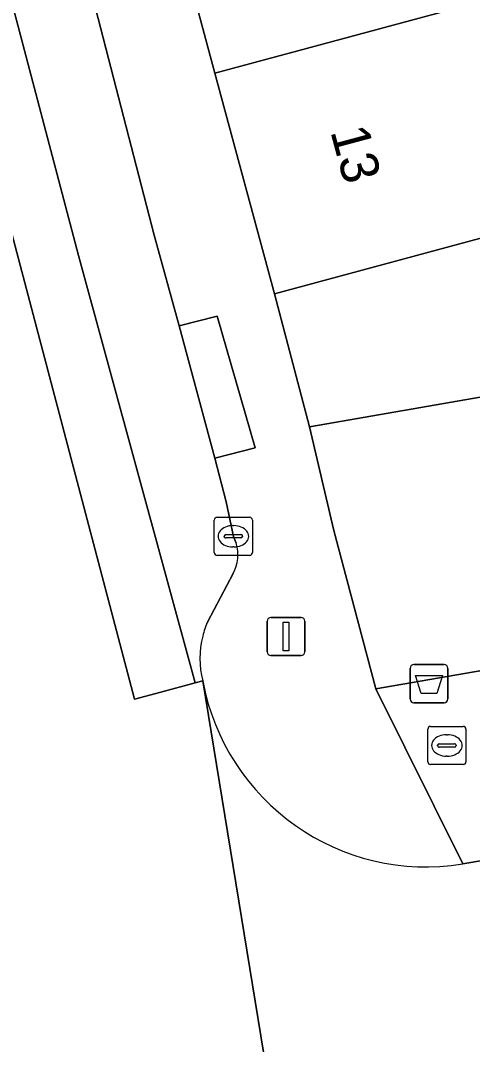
# Model space of a CAD drawing. Extents: x 159371 to 159986, y 382987 to 383597.
# Drawn here: x 159702.32 to 159714.18, y 383315.4 to 383342.22 of the extents above; entities that cross this region are included whole.
import ezdxf

# ---------------------------------------------------------------- set-up
doc = ezdxf.new("R2010")
doc.units = 0
for name, color, linetype in [('IMGEO_Afvalbak', 7, 'Continuous'), ('IMGEO_Brandkraan', 7, 'Continuous'), ('IMGEO_Erf', 7, 'Continuous'), ('IMGEO_Kolk', 7, 'Continuous'), ('IMGEO_Lichtmast', 7, 'Continuous'), ('IMGEO_Pand', 7, 'Continuous'), ('IMGEO_Pand_nummerreeks', 7, 'Continuous'), ('IMGEO_Parkeervlak_gesloten', 7, 'Continuous'), ('IMGEO_Rijbaan_lokaal_gesloten', 7, 'Continuous'), ('IMGEO_Rijbaan_lokaal_open', 7, 'Continuous'), ('IMGEO_Voetpad_open', 7, 'Continuous')]:
    doc.layers.add(name, color=color, linetype=linetype)

msp = doc.modelspace()

# ---------------------------------------------------------------- linework, layer by layer
at = {"layer": 'IMGEO_Afvalbak'}
for p, q in [((159712.638, 383325.349), (159713.428, 383325.349)), ((159713.428, 383325.349), (159712.638, 383325.349)), ((159712.538, 383324.449), (159712.538, 383325.249)), ((159712.538, 383325.249), (159712.538, 383324.449)), ((159713.528, 383325.249), (159713.528, 383324.449)), ((159713.528, 383324.449), (159713.528, 383325.249)), ((159713.428, 383324.349), (159712.638, 383324.349)), ((159712.638, 383324.349), (159713.428, 383324.349))]:
    msp.add_line(p, q, dxfattribs=at)
msp.add_lwpolyline([(159712.681, 383325.063), (159713.385, 383325.063), (159713.236, 383324.593), (159712.83, 383324.593), (159712.681, 383325.063)], dxfattribs=at)
for centre, start, end in [((159712.638, 383325.249), 90, 180), ((159712.638, 383325.249), 90, 180), ((159713.428, 383325.249), 0, 90), ((159713.428, 383325.249), 360, 90), ((159712.638, 383324.449), 180, 270), ((159712.638, 383324.449), 180, 270), ((159713.428, 383324.449), 270, 0), ((159713.428, 383324.449), 270, 0)]:
    msp.add_arc(centre, 0.1, start, end, dxfattribs=at)
at = {"layer": 'IMGEO_Brandkraan'}
for p, q in [((159713.077, 383323.73), (159713.929, 383323.73)), ((159713.002, 383322.804), (159713.002, 383323.656)), ((159713.49, 383323.51), (159713.515, 383323.51)), ((159714.003, 383323.656), (159714.003, 383322.804)), ((159713.261, 383323.224), (159713.261, 383323.236)), ((159713.699, 383323.187), (159713.301, 383323.187)), ((159713.304, 383323.273), (159713.702, 383323.273)), ((159713.745, 383323.236), (159713.745, 383323.224)), ((159713.513, 383322.95), (159713.488, 383322.95)), ((159713.929, 383322.73), (159713.077, 383322.73))]:
    msp.add_line(p, q, dxfattribs=at)
for points in [[(159713.077, 383323.73), (159713.929, 383323.73)], [(159713.002, 383322.804), (159713.002, 383323.656)], [(159714.003, 383323.656), (159714.003, 383322.804)], [(159713.929, 383322.73), (159713.077, 383322.73)]]:
    msp.add_lwpolyline(points, dxfattribs=at)
for centre, radius, start, end in [((159713.079, 383323.654), 0.0765, 91.552, 178.448), ((159713.079, 383323.654), 0.0765, 91.552, 178.448), ((159713.927, 383323.654), 0.0765, 1.552, 88.448), ((159713.927, 383323.654), 0.0765, 1.552, 88.448), ((159713.301, 383323.233), 0.0403, 85.8775, 175.7526), ((159713.298, 383323.223), 0.0366, 178.938, 274.7102), ((159713.702, 383323.23), 0.043, 264.8664, 352.4533), ((159713.706, 383323.235), 0.0386, 1.7309, 96.639), ((159713.079, 383322.806), 0.0765, 181.552, 268.448), ((159713.079, 383322.806), 0.0765, 181.552, 268.448), ((159713.927, 383322.806), 0.0765, 271.552, 358.448), ((159713.927, 383322.806), 0.0765, 271.552, 358.448)]:
    msp.add_arc(centre, radius, start, end, dxfattribs=at)
for centre, major_axis, ratio, start_param, end_param in [((159713.489, 383323.23), (-0.387, 0.002), 0.722429, 4.712389, 7.853982), ((159713.514, 383323.23), (-0.39, 0.002), 0.717154, 1.570796, 4.712389)]:
    msp.add_ellipse(centre, major_axis=major_axis, ratio=ratio, start_param=start_param, end_param=end_param, dxfattribs=at)
at = {"layer": 'IMGEO_Erf'}
msp.add_lwpolyline([(159719.014, 383337.764), (159713.808, 383336.362), (159708.979, 383335.062), (159709.903, 383331.579), (159714.831, 383332.427)], dxfattribs=at)
at = {"layer": 'IMGEO_Kolk'}
for p, q in [((159707.404, 383328.282), (159707.404, 383329.134)), ((159707.479, 383329.208), (159708.331, 383329.208)), ((159708.405, 383329.134), (159708.405, 383328.282)), ((159707.892, 383328.988), (159707.917, 383328.988)), ((159707.663, 383328.702), (159707.663, 383328.714)), ((159708.101, 383328.665), (159707.703, 383328.665)), ((159707.706, 383328.751), (159708.104, 383328.751)), ((159708.147, 383328.714), (159708.147, 383328.702)), ((159707.915, 383328.428), (159707.89, 383328.428)), ((159708.331, 383328.208), (159707.479, 383328.208))]:
    msp.add_line(p, q, dxfattribs=at)
for points in [[(159707.404, 383328.282), (159707.404, 383329.134)], [(159707.479, 383329.208), (159708.331, 383329.208)], [(159708.405, 383329.134), (159708.405, 383328.282)], [(159708.331, 383328.208), (159707.479, 383328.208)]]:
    msp.add_lwpolyline(points, dxfattribs=at)
for centre, radius, start, end in [((159707.481, 383329.132), 0.0765, 91.552, 178.448), ((159707.481, 383329.132), 0.0765, 91.552, 178.448), ((159708.329, 383329.132), 0.0765, 1.552, 88.448), ((159708.329, 383329.132), 0.0765, 1.552, 88.448), ((159707.703, 383328.711), 0.0403, 85.8775, 175.7526), ((159707.7, 383328.701), 0.0366, 178.938, 274.7102), ((159708.104, 383328.708), 0.043, 264.8664, 352.4533), ((159708.108, 383328.713), 0.0386, 1.7309, 96.639), ((159707.481, 383328.284), 0.0765, 181.552, 268.448), ((159707.481, 383328.284), 0.0765, 181.552, 268.448), ((159708.329, 383328.284), 0.0765, 271.552, 358.448), ((159708.329, 383328.284), 0.0765, 271.552, 358.448)]:
    msp.add_arc(centre, radius, start, end, dxfattribs=at)
for centre, major_axis, ratio, start_param, end_param in [((159707.891, 383328.708), (-0.387, 0.002), 0.722429, 4.712389, 7.853982), ((159707.916, 383328.708), (-0.39, 0.002), 0.717154, 1.570796, 4.712389)]:
    msp.add_ellipse(centre, major_axis=major_axis, ratio=ratio, start_param=start_param, end_param=end_param, dxfattribs=at)
at = {"layer": 'IMGEO_Lichtmast'}
for p, q in [((159708.791, 383325.683), (159708.791, 383326.483)), ((159708.791, 383326.483), (159708.791, 383325.683)), ((159708.891, 383326.583), (159709.681, 383326.583)), ((159709.681, 383326.583), (159708.891, 383326.583)), ((159709.781, 383326.483), (159709.781, 383325.683)), ((159709.781, 383325.683), (159709.781, 383326.483)), ((159709.681, 383325.583), (159708.891, 383325.583)), ((159708.891, 383325.583), (159709.681, 383325.583))]:
    msp.add_line(p, q, dxfattribs=at)
msp.add_lwpolyline([(159709.211, 383326.458), (159709.361, 383326.458), (159709.361, 383325.708), (159709.211, 383325.708), (159709.211, 383326.458)], dxfattribs=at)
for centre, start, end in [((159708.891, 383326.483), 90, 180), ((159708.891, 383326.483), 90, 180), ((159709.681, 383326.483), 0, 90), ((159709.681, 383326.483), 360, 90), ((159708.891, 383325.683), 180, 270), ((159708.891, 383325.683), 180, 270), ((159709.681, 383325.683), 270, 0), ((159709.681, 383325.683), 270, 0)]:
    msp.add_arc(centre, 0.1, start, end, dxfattribs=at)
at = {"layer": 'IMGEO_Pand'}
for points in [[(159714.953, 383342.87), (159714.176, 383345.756), (159719.14, 383347.093), (159718.36, 383349.99), (159710.693, 383347.925), (159705.865, 383346.625), (159707.422, 383340.842)], [(159714.953, 383342.87), (159707.422, 383340.842), (159708.979, 383335.062), (159713.808, 383336.362), (159719.014, 383337.764), (159719.743, 383335.112), (159725.982, 383336.838), (159724.964, 383340.52), (159721.207, 383339.481), (159720.737, 383341.229), (159715.756, 383339.888)], [(159737.964, 383336.387), (159737.482, 383336.304), (159725.518, 383334.249), (159725.285, 383335.492), (159722.422, 383334.751), (159722.582, 383333.762), (159714.831, 383332.427), (159709.903, 383331.579), (159710.541, 383328.856), (159711.636, 383324.71), (159736.824, 383329.061), (159739.771, 383329.567)]]:
    msp.add_lwpolyline(points, close=True, dxfattribs=at)
at = {"layer": 'IMGEO_Parkeervlak_gesloten'}
for points in [[(159690.128, 383395.731), (159689.221, 383399.138), (159688.963, 383400.109), (159679.139, 383437.543), (159674.718, 383453.996), (159673.929, 383456.929), (159673.465, 383458.741), (159672.103, 383458.409), (159671.763, 383458.326), (159671.587, 383458.28), (159673.093, 383452.571), (159675.902, 383441.929), (159681.054, 383422.407), (159689.359, 383390.944), (159696.414, 383364.212), (159703.844, 383336.06), (159706.907, 383324.871), (159707.101, 383324.923)], [(159707.981, 383328.527), (159707.905, 383328.707), (159707.718, 383329.61), (159707.422, 383330.754), (159707.334, 383331.079), (159706.48, 383334.224), (159705.825, 383336.598), (159702.961, 383347.681), (159700.034, 383358.613), (159695.004, 383377.404), (159690.128, 383395.731)], [(159707.233, 383326.475), (159707.9, 383327.735)]]:
    msp.add_lwpolyline(points, dxfattribs=at)
for centre, radius, start, end in [((159706.954, 383328.232), 1.069, 332.2879, 16.0331), ((159709.422, 383325.505), 2.395, 156.097, 165.7778), ((159709.409, 383325.508), 2.381, 165.7741, 194.2259)]:
    msp.add_arc(centre, radius, start, end, dxfattribs=at)
at = {"layer": 'IMGEO_Rijbaan_lokaal_gesloten'}
msp.add_lwpolyline([(159671.587, 383458.28), (159670.74, 383458.056), (159670.094, 383457.885), (159670.625, 383455.872), (159678.409, 383426.38), (159686.465, 383395.857), (159692.786, 383371.909), (159698.534, 383350.133), (159705.315, 383324.44), (159706.001, 383324.626), (159706.907, 383324.871), (159703.844, 383336.06), (159696.414, 383364.212), (159689.359, 383390.944), (159681.054, 383422.407), (159675.902, 383441.929), (159673.093, 383452.571)], close=True, dxfattribs=at)
msp.add_lwpolyline([(159710.058, 383306.882), (159710.001, 383307.233), (159707.101, 383324.923), (159706.907, 383324.871), (159706.001, 383324.626), (159705.315, 383324.44), (159698.534, 383350.133), (159692.786, 383371.909), (159686.465, 383395.857), (159678.409, 383426.38), (159670.625, 383455.872), (159670.094, 383457.885), (159667.027, 383457.076), (159667.185, 383456.552), (159693.274, 383357.013), (159696.447, 383345.036), (159702.049, 383323.57), (159700.731, 383323.191)], dxfattribs=at)
at = {"layer": 'IMGEO_Rijbaan_lokaal_open'}
for points in [[(159741.677, 383325.175), (159733.589, 383323.663), (159733.422, 383323.631), (159720.685, 383321.319), (159715.529, 383320.396), (159715.107, 383320.328), (159713.918, 383320.127)], [(159707.101, 383324.923), (159710.001, 383307.233)]]:
    msp.add_lwpolyline(points, dxfattribs=at)
msp.add_arc((159712.96, 383326.008), 5.959, 190.4926, 279.2519, dxfattribs=at)
at = {"layer": 'IMGEO_Voetpad_open'}
for points in [[(159713.918, 383320.127), (159711.636, 383324.71), (159710.541, 383328.856), (159709.903, 383331.579), (159708.979, 383335.062), (159707.422, 383340.842), (159705.865, 383346.625), (159705.59, 383347.631), (159704.034, 383353.41), (159702.478, 383359.191), (159701.962, 383361.143), (159700.256, 383367.478), (159698.591, 383373.663), (159698.326, 383374.668), (159696.764, 383380.472), (159695.202, 383386.273), (159695.793, 383386.432), (159689.89, 383408.493), (159681.184, 383441.029)], [(159690.128, 383395.731), (159695.004, 383377.404), (159700.034, 383358.613), (159702.961, 383347.681), (159705.825, 383336.598), (159706.48, 383334.224), (159707.481, 383334.478), (159708.477, 383331.026), (159707.422, 383330.754), (159707.718, 383329.61), (159707.905, 383328.707), (159707.981, 383328.527)], [(159775.202, 383336.678), (159771.268, 383335.626), (159765.592, 383334.421), (159759.444, 383333.116), (159757.449, 383332.738), (159751.293, 383331.713), (159750.341, 383331.547), (159744.223, 383330.379), (159739.771, 383329.567), (159736.824, 383329.061), (159711.636, 383324.71), (159713.918, 383320.127), (159715.107, 383320.328), (159715.529, 383320.396)], [(159707.9, 383327.735), (159707.233, 383326.475)]]:
    msp.add_lwpolyline(points, dxfattribs=at)
msp.add_lwpolyline([(159706.48, 383334.224), (159707.334, 383331.079), (159707.422, 383330.754), (159708.477, 383331.026), (159707.481, 383334.478)], close=True, dxfattribs=at)
for centre, radius, start, end in [((159706.954, 383328.232), 1.069, 332.2879, 16.0331), ((159709.422, 383325.505), 2.395, 156.097, 165.7778), ((159709.409, 383325.508), 2.381, 165.7741, 194.2259), ((159712.96, 383326.008), 5.959, 190.4926, 279.2519)]:
    msp.add_arc(centre, radius, start, end, dxfattribs=at)

# ---------------------------------------------------------------- texts
at = {"layer": 'IMGEO_Pand_nummerreeks'}
msp.add_text('13', height=1, rotation=285.0763, dxfattribs=at).set_placement((159710.443, 383339.317))

doc.saveas('drawing.dxf')
